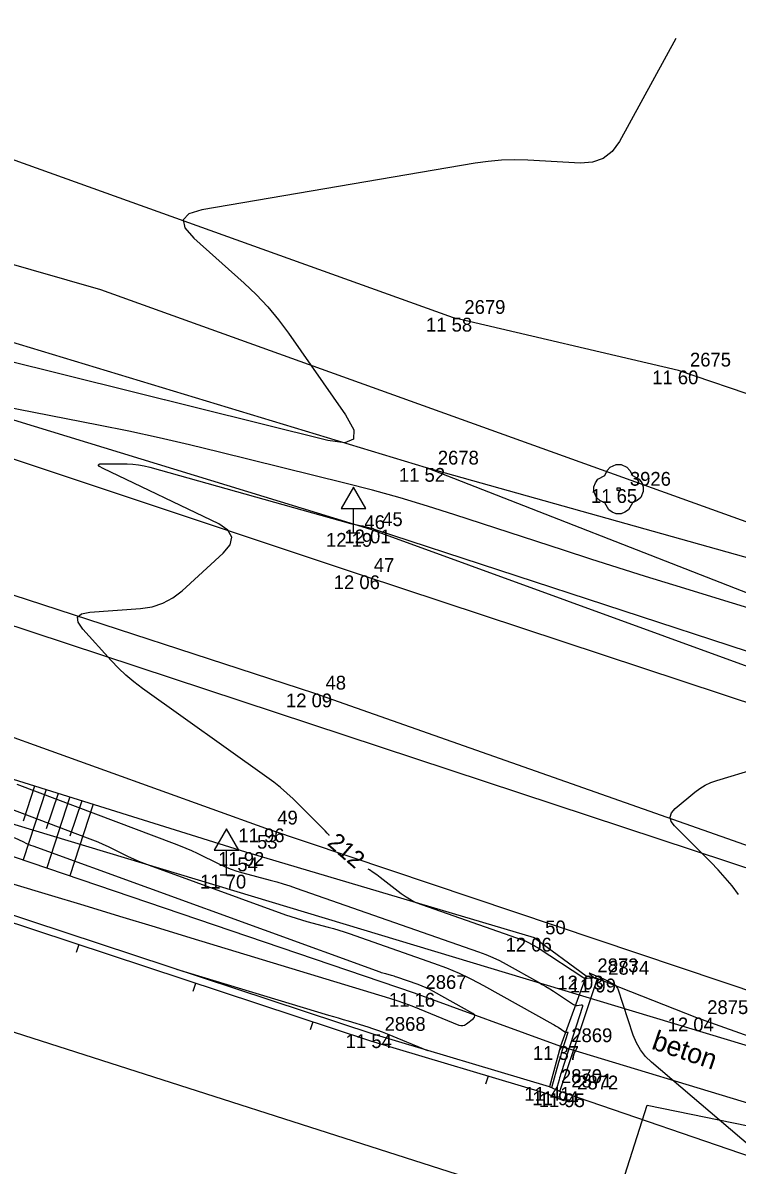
# Model space of a CAD drawing. Extents: x -703403 to -701924, y -1022520 to -1021856.
# Drawn here: x -702048.06 to -702033.55, y -1022309.37 to -1022286.17 of the extents above; entities that cross this region are included whole.
import ezdxf

# ---------------------------------------------------------------- set-up
doc = ezdxf.new("R2010")
doc.units = 0
for name, color, linetype in [('Ex_Contour Labels', 7, 'Continuous'), ('Ex_Major Contours', 7, 'Continuous'), ('Ex_Minor Contours', 7, 'Continuous'), ('Z_betonova_konstrukce', 7, 'Continuous'), ('Z_body', 7, 'Continuous'), ('Z_body_cisla', 7, 'Continuous'), ('Z_body_vysky_redukovane', 7, 'Continuous'), ('Z_dopravni_znacky', 7, 'Continuous'), ('Z_hrany_paty', 7, 'Continuous'), ('Z_katastr_hranice', 7, 'Continuous'), ('Z_katastr_vnitrni_kresba', 7, 'Continuous'), ('Z_komunikace', 7, 'Continuous'), ('Z_komunikace_osa', 7, 'Continuous'), ('Z_ploty', 7, 'Continuous'), ('Z_ploty_znacky', 7, 'Continuous'), ('Z_pole_rozhranni', 7, 'Continuous'), ('Z_popisy', 7, 'Continuous'), ('Z_propustek', 7, 'Continuous'), ('Z_rozhranni', 7, 'Continuous'), ('Z_technicke_srafy', 7, 'Continuous'), ('Z_vstupy', 7, 'Continuous'), ('Z_zelen_jednotliva', 7, 'Continuous')]:
    doc.layers.add(name, color=color, linetype=linetype)

# ---------------------------------------------------------------- blocks, each defined once
blk = doc.blocks.new('POINT_DISPLAY')
blk.add_line((0, 0), (0, 0))
blk = doc.blocks.new('Z24')
for p, q in [((-0.17, 0.45), (-0.05, 0.5)), ((-0.05, 0.5), (0.05, 0.5)), ((0.05, 0.5), (0.17, 0.45)), ((-0.42, 0.2), (-0.28, 0.28)), ((-0.28, 0.28), (-0.23, 0.38)), ((-0.23, 0.38), (-0.17, 0.45)), ((0.17, 0.45), (0.23, 0.38)), ((0.23, 0.38), (0.28, 0.28)), ((0.28, 0.28), (0.42, 0.2)), ((-0.5, 0.05), (-0.47, 0.13)), ((-0.5, -0.05), (-0.5, 0.05)), ((-0.47, 0.13), (-0.42, 0.2)), ((-0.03, -0.03), (-0.03, 0.03)), ((-0.03, 0.03), (0.03, 0.03)), ((0.03, 0.03), (0.03, -0.03)), ((0.42, 0.2), (0.47, 0.13)), ((0.47, 0.13), (0.5, 0.05)), ((0.5, 0.05), (0.5, -0.05)), ((-0.45, -0.17), (-0.5, -0.05)), ((-0.38, -0.23), (-0.45, -0.17)), ((-0.28, -0.28), (-0.38, -0.23)), ((0.03, -0.03), (-0.03, -0.03)), ((0.38, -0.23), (0.28, -0.28)), ((0.45, -0.17), (0.38, -0.23)), ((0.5, -0.05), (0.45, -0.17)), ((-0.2, -0.42), (-0.28, -0.28)), ((-0.13, -0.47), (-0.2, -0.42)), ((0.2, -0.42), (0.13, -0.47)), ((0.28, -0.28), (0.2, -0.42)), ((-0.05, -0.5), (-0.13, -0.47)), ((0.05, -0.5), (-0.05, -0.5)), ((0.13, -0.47), (0.05, -0.5))]:
    blk.add_line(p, q)
blk = doc.blocks.new('Z527')
for p, q in [((0, 0.93), (-0.25, 0.5)), ((0.25, 0.5), (0, 0.93)), ((-0.25, 0.5), (0.25, 0.5)), ((0, 0), (0, 0.5)), ((-0.13, 0), (0.13, 0))]:
    blk.add_line(p, q)
blk = doc.blocks.new('Z210')
blk.add_line((0, 0), (0, 0.17))

msp = doc.modelspace()

# ---------------------------------------------------------------- linework, layer by layer
at = {"layer": 'Ex_Major Contours'}
for points in [[(-702041.834, -1022302.671), (-702041.835, -1022302.67), (-702041.876, -1022302.624), (-702041.918, -1022302.581), (-702042.569, -1022301.932), (-702042.695, -1022301.812), (-702042.825, -1022301.698), (-702042.959, -1022301.589), (-702043.098, -1022301.486), (-702045.628, -1022299.685), (-702045.799, -1022299.556), (-702045.961, -1022299.419), (-702046.116, -1022299.273), (-702046.263, -1022299.119), (-702046.835, -1022298.484), (-702046.933, -1022298.343), (-702046.943, -1022298.238), (-702046.863, -1022298.169), (-702046.694, -1022298.136), (-702045.667, -1022298.065), (-702045.432, -1022298.029), (-702045.213, -1022297.957), (-702045.01, -1022297.849), (-702044.823, -1022297.703), (-702043.989, -1022296.943), (-702043.846, -1022296.769), (-702043.813, -1022296.612), (-702043.89, -1022296.472), (-702044.077, -1022296.347), (-702046.424, -1022295.221), (-702046.501, -1022295.177), (-702046.523, -1022295.146), (-702046.489, -1022295.128), (-702046.401, -1022295.123), (-702045.935, -1022295.128), (-702045.82, -1022295.133), (-702045.705, -1022295.146), (-702045.591, -1022295.166), (-702045.479, -1022295.193), (-702041.4, -1022296.336), (-702041.375, -1022296.342), (-702041.351, -1022296.348), (-702041.327, -1022296.354), (-702041.302, -1022296.359), (-702041.203, -1022296.378), (-702041.179, -1022296.383), (-702041.155, -1022296.388), (-702041.132, -1022296.394), (-702041.108, -1022296.399), (-702041.014, -1022296.423), (-702040.991, -1022296.429), (-702040.967, -1022296.435), (-702040.944, -1022296.442), (-702040.921, -1022296.45), (-702033.347, -1022298.929)], [(-702033.274, -1022308.995), (-702035.289, -1022307.279), (-702035.412, -1022307.16), (-702035.515, -1022307.028), (-702035.598, -1022306.883), (-702035.662, -1022306.725), (-702035.969, -1022305.797), (-702035.98, -1022305.769), (-702035.997, -1022305.745), (-702036.017, -1022305.724), (-702036.041, -1022305.707), (-702036.148, -1022305.645), (-702036.175, -1022305.63), (-702036.203, -1022305.616), (-702036.231, -1022305.603), (-702036.259, -1022305.591), (-702036.535, -1022305.477), (-702036.55, -1022305.472), (-702036.556, -1022305.472), (-702036.553, -1022305.477), (-702036.542, -1022305.487), (-702036.479, -1022305.539), (-702036.468, -1022305.551), (-702036.465, -1022305.56), (-702036.472, -1022305.566), (-702036.488, -1022305.569), (-702036.595, -1022305.58), (-702036.619, -1022305.58), (-702036.642, -1022305.577), (-702036.664, -1022305.569), (-702036.685, -1022305.558), (-702037.574, -1022304.974), (-702037.599, -1022304.958), (-702037.624, -1022304.942), (-702037.65, -1022304.927), (-702037.676, -1022304.912), (-702037.78, -1022304.854), (-702037.807, -1022304.84), (-702037.834, -1022304.827), (-702037.861, -1022304.815), (-702037.889, -1022304.805), (-702039.955, -1022304.083), (-702040.066, -1022304.04), (-702040.172, -1022303.987), (-702040.274, -1022303.927), (-702040.371, -1022303.858), (-702040.801, -1022303.526), (-702040.871, -1022303.473), (-702040.943, -1022303.422), (-702041.016, -1022303.374), (-702041.041, -1022303.359)]]:
    msp.add_lwpolyline(points, dxfattribs=at)
at = {"layer": 'Ex_Minor Contours'}
for points in [[(-702034.795, -1022286.488), (-702035.943, -1022288.577), (-702036.089, -1022288.781), (-702036.27, -1022288.922), (-702036.486, -1022289.001), (-702036.736, -1022289.018), (-702037.805, -1022288.959), (-702038.072, -1022288.952), (-702038.338, -1022288.96), (-702038.604, -1022288.983), (-702038.868, -1022289.02), (-702044.42, -1022289.969), (-702044.684, -1022290.048), (-702044.799, -1022290.17), (-702044.766, -1022290.334), (-702044.585, -1022290.541), (-702043.564, -1022291.455), (-702043.316, -1022291.69), (-702043.083, -1022291.938), (-702042.865, -1022292.199), (-702042.661, -1022292.474), (-702041.507, -1022294.128), (-702041.337, -1022294.437), (-702041.34, -1022294.628), (-702041.516, -1022294.698), (-702041.866, -1022294.65), (-702048.5, -1022293.003)], [(-702030.013, -1022299.075), (-702034.861, -1022297.585), (-702035.416, -1022297.412), (-702035.971, -1022297.238), (-702036.524, -1022297.061), (-702037.077, -1022296.881), (-702039.286, -1022296.158), (-702039.84, -1022295.983), (-702040.396, -1022295.817), (-702040.956, -1022295.662), (-702041.518, -1022295.517), (-702044.06, -1022294.886), (-702044.673, -1022294.738), (-702045.287, -1022294.598), (-702045.903, -1022294.465), (-702046.521, -1022294.34), (-702050.119, -1022293.637)], [(-702052.253, -1022300.639), (-702046.746, -1022302.719), (-702046.64, -1022302.761), (-702046.534, -1022302.805), (-702046.43, -1022302.851), (-702046.326, -1022302.899), (-702045.914, -1022303.098), (-702045.81, -1022303.146), (-702045.706, -1022303.192), (-702045.6, -1022303.235), (-702045.493, -1022303.275), (-702042.72, -1022304.282), (-702042.614, -1022304.319), (-702042.507, -1022304.354), (-702042.4, -1022304.387), (-702042.292, -1022304.417), (-702041.857, -1022304.533), (-702041.749, -1022304.563), (-702041.641, -1022304.595), (-702041.534, -1022304.629), (-702041.428, -1022304.665), (-702039.715, -1022305.263), (-702039.454, -1022305.36), (-702039.198, -1022305.469), (-702038.947, -1022305.588), (-702038.701, -1022305.719), (-702037.293, -1022306.506), (-702037.266, -1022306.521), (-702037.24, -1022306.536), (-702037.215, -1022306.552), (-702037.189, -1022306.569), (-702037.049, -1022306.661), (-702037.043, -1022306.664), (-702037.037, -1022306.666), (-702037.031, -1022306.667), (-702037.024, -1022306.667), (-702036.996, -1022306.664), (-702036.991, -1022306.664), (-702036.987, -1022306.666), (-702036.986, -1022306.67), (-702036.987, -1022306.676), (-702037.102, -1022307.036), (-702037.122, -1022307.098), (-702037.141, -1022307.16), (-702037.16, -1022307.223), (-702037.178, -1022307.285), (-702037.324, -1022307.795)], [(-702033.525, -1022303.869), (-702033.656, -1022303.697), (-702033.793, -1022303.53), (-702033.937, -1022303.369), (-702034.088, -1022303.213), (-702034.826, -1022302.478), (-702034.894, -1022302.387), (-702034.914, -1022302.299), (-702034.887, -1022302.212), (-702034.811, -1022302.128), (-702034.414, -1022301.795), (-702034.311, -1022301.718), (-702034.203, -1022301.652), (-702034.088, -1022301.597), (-702033.967, -1022301.554), (-702031.551, -1022300.827)], [(-702048.177, -1022301.629), (-702044.982, -1022302.835), (-702044.864, -1022302.881), (-702044.747, -1022302.93), (-702044.631, -1022302.981), (-702044.517, -1022303.035), (-702044.06, -1022303.255), (-702043.945, -1022303.308), (-702043.827, -1022303.354), (-702043.708, -1022303.395), (-702043.586, -1022303.431), (-702043.032, -1022303.579), (-702042.899, -1022303.615), (-702042.767, -1022303.655), (-702042.635, -1022303.696), (-702042.505, -1022303.741), (-702038.802, -1022305.034), (-702038.658, -1022305.088), (-702038.516, -1022305.148), (-702038.377, -1022305.214), (-702038.241, -1022305.286), (-702037.586, -1022305.652), (-702037.509, -1022305.696), (-702037.434, -1022305.741), (-702037.358, -1022305.788), (-702037.284, -1022305.835), (-702036.874, -1022306.105), (-702036.857, -1022306.114), (-702036.839, -1022306.12), (-702036.82, -1022306.123), (-702036.801, -1022306.123), (-702036.72, -1022306.114), (-702036.704, -1022306.115), (-702036.693, -1022306.121), (-702036.69, -1022306.132), (-702036.693, -1022306.149), (-702037.125, -1022307.495), (-702037.136, -1022307.529), (-702037.146, -1022307.563), (-702037.156, -1022307.598), (-702037.166, -1022307.632), (-702037.225, -1022307.838)], [(-702053.415, -1022302.106), (-702047.538, -1022303.873), (-702046.814, -1022304.091), (-702046.091, -1022304.31), (-702045.368, -1022304.529), (-702044.644, -1022304.749), (-702040.613, -1022305.976), (-702040.461, -1022306.024), (-702040.309, -1022306.076), (-702040.159, -1022306.132), (-702040.01, -1022306.191), (-702039.204, -1022306.523), (-702039.163, -1022306.535), (-702039.123, -1022306.535), (-702039.085, -1022306.524), (-702039.049, -1022306.501), (-702038.908, -1022306.389), (-702038.882, -1022306.362), (-702038.875, -1022306.336), (-702038.886, -1022306.312), (-702038.916, -1022306.289), (-702039.716, -1022305.842), (-702039.792, -1022305.802), (-702039.869, -1022305.765), (-702039.948, -1022305.731), (-702040.028, -1022305.701), (-702040.459, -1022305.551), (-702040.487, -1022305.541), (-702040.515, -1022305.532), (-702040.544, -1022305.524), (-702040.573, -1022305.516), (-702040.688, -1022305.485), (-702040.716, -1022305.477), (-702040.745, -1022305.469), (-702040.773, -1022305.46), (-702040.801, -1022305.45), (-702047.845, -1022302.892), (-702047.893, -1022302.874), (-702047.942, -1022302.854), (-702047.99, -1022302.833), (-702048.037, -1022302.811), (-702048.225, -1022302.72)], [(-702044.937, -1022305.39), (-702041.85, -1022306.319), (-702041.75, -1022306.349), (-702041.65, -1022306.379), (-702041.551, -1022306.409), (-702041.451, -1022306.439), (-702041.052, -1022306.561), (-702040.953, -1022306.592), (-702040.854, -1022306.626), (-702040.757, -1022306.662), (-702040.66, -1022306.701), (-702039.838, -1022307.039)]]:
    msp.add_lwpolyline(points, dxfattribs=at)
at = {"layer": 'Z_betonova_konstrukce'}
for p, q in [((-702037.15, -1022307.87), (-702036.39, -1022305.58)), ((-702036.62, -1022305.52), (-702037.14, -1022306.95)), ((-702036.62, -1022305.52), (-702036.39, -1022305.58)), ((-702037.14, -1022306.95), (-702037.36, -1022307.78))]:
    msp.add_line(p, q, dxfattribs=at)
at = {"layer": 'Z_hrany_paty'}
for p, q in [((-702039.86, -1022295.21), (-702052.88, -1022291.26)), ((-702040.99, -1022296.46), (-702053.28, -1022292.7)), ((-702022.69, -1022301.91), (-702039.86, -1022295.21)), ((-702031.79, -1022297.47), (-702039.86, -1022295.21)), ((-702029.38, -1022300.69), (-702040.99, -1022296.46)), ((-702043.53, -1022303.01), (-702054.01, -1022299.73)), ((-702049.82, -1022302.57), (-702040.11, -1022305.87)), ((-702037.67, -1022304.75), (-702043.53, -1022303.01)), ((-702037.67, -1022304.75), (-702036.62, -1022305.52)), ((-702040.11, -1022305.87), (-702037.14, -1022306.95))]:
    msp.add_line(p, q, dxfattribs=at)
at = {"layer": 'Z_katastr_hranice'}
for p, q in [((-702046.47, -1022291.59), (-702114.48, -1022272.11)), ((-702081.55, -1022287.42), (-702015.88, -1022309.1)), ((-701974.6, -1022317.46), (-702046.47, -1022291.59)), ((-702016.82, -1022311.93), (-702057.09, -1022299.78)), ((-702036.14, -1022310.54), (-702035.38, -1022308.15)), ((-702035.38, -1022308.15), (-702016.82, -1022311.93))]:
    msp.add_line(p, q, dxfattribs=at)
at = {"layer": 'Z_katastr_vnitrni_kresba'}
msp.add_line((-702055.91, -1022304.21), (-702036.14, -1022310.54), dxfattribs=at)
at = {"layer": 'Z_komunikace'}
for p, q in [((-702041.16, -1022297.39), (-702053.32, -1022293.34)), ((-702029.57, -1022301.23), (-702041.16, -1022297.39)), ((-702043.12, -1022302.53), (-702053.67, -1022298.73)), ((-702031.31, -1022306.5), (-702043.12, -1022302.53))]:
    msp.add_line(p, q, dxfattribs=at)
at = {"layer": 'Z_komunikace_osa'}
for p, q in [((-702042.13, -1022299.79), (-702054.33, -1022295.82)), ((-702030.56, -1022303.86), (-702042.13, -1022299.79))]:
    msp.add_line(p, q, dxfattribs=at)
at = {"layer": 'Z_ploty'}
for p, q in [((-702040.99, -1022306.85), (-702055.98, -1022301.9)), ((-702040.94, -1022306.71), (-702055.93, -1022301.76)), ((-702037.36, -1022307.78), (-702040.94, -1022306.71)), ((-702037.41, -1022307.92), (-702040.99, -1022306.85)), ((-702037.21, -1022308.01), (-702037.41, -1022307.92)), ((-702037.15, -1022307.87), (-702037.36, -1022307.78)), ((-702037.02, -1022307.91), (-702037.15, -1022307.87)), ((-702037.07, -1022308.06), (-702037.02, -1022307.91)), ((-702037.07, -1022308.06), (-702037.21, -1022308.01))]:
    msp.add_line(p, q, dxfattribs=at)
at = {"layer": 'Z_pole_rozhranni'}
for p, q in [((-702039.31, -1022292.16), (-702053.05, -1022287.23)), ((-702034.74, -1022293.23), (-702039.31, -1022292.16)), ((-702021.67, -1022297.67), (-702034.74, -1022293.23))]:
    msp.add_line(p, q, dxfattribs=at)
at = {"layer": 'Z_propustek'}
msp.add_line((-702037.14, -1022306.95), (-702032.28, -1022308.43), dxfattribs=at)
at = {"layer": 'Z_rozhranni'}
for p, q in [((-702036.39, -1022305.58), (-702034.38, -1022306.37)), ((-702034.38, -1022306.37), (-702032.17, -1022307.16))]:
    msp.add_line(p, q, dxfattribs=at)
at = {"layer": 'Z_technicke_srafy'}
for p, q in [((-702047.82, -1022301.67), (-702048.05, -1022302.38)), ((-702047.58, -1022301.74), (-702048.05, -1022303.17)), ((-702047.34, -1022301.82), (-702047.58, -1022302.54)), ((-702047.1, -1022301.89), (-702047.57, -1022303.33)), ((-702046.86, -1022301.97), (-702047.1, -1022302.69)), ((-702046.63, -1022302.04), (-702047.1, -1022303.49))]:
    msp.add_line(p, q, dxfattribs=at)
at = {"layer": 'Z_vstupy'}
msp.add_line((-702037.02, -1022307.91), (-702032.88, -1022309.33), dxfattribs=at)

# ---------------------------------------------------------------- block references
at = {"layer": 'Z_body'}
for p in [(-702039.31, -1022292.16), (-702034.74, -1022293.23), (-702039.86, -1022295.21), (-702035.96, -1022295.64), (-702041.34, -1022296.53), (-702040.99, -1022296.46), (-702041.16, -1022297.39), (-702042.13, -1022299.79), (-702043.12, -1022302.53), (-702043.53, -1022303.01), (-702043.92, -1022303.47), (-702037.67, -1022304.75), (-702036.62, -1022305.52), (-702036.39, -1022305.58), (-702040.11, -1022305.87), (-702034.38, -1022306.37), (-702040.94, -1022306.71), (-702037.14, -1022306.95), (-702037.36, -1022307.78), (-702037.15, -1022307.87), (-702037.02, -1022307.91)]:
    msp.add_blockref('POINT_DISPLAY', p, dxfattribs=at)
at = {"layer": 'Z_dopravni_znacky'}
for p in [(-702041.34, -1022296.53), (-702043.92, -1022303.47)]:
    msp.add_blockref('Z527', p, dxfattribs=at)
at = {"layer": 'Z_ploty_znacky'}
for p, rotation in [((-702046.92, -1022304.89), 161.7), ((-702044.55, -1022305.68), 161.7), ((-702042.17, -1022306.46), 161.7), ((-702038.61, -1022307.56), 163.3)]:
    msp.add_blockref('Z210', p, dxfattribs=dict(at, rotation=rotation))
at = {"layer": 'Z_zelen_jednotliva'}
msp.add_blockref('Z24', (-702035.96, -1022295.64), dxfattribs=at)

# ---------------------------------------------------------------- texts
at = {"layer": 'Ex_Contour Labels'}
msp.add_text('212', height=0.35, rotation=319.0617, dxfattribs=at).set_placement((-702041.894, -1022302.852))
at = {"layer": 'Z_body_cisla'}
for s, p in [('2679', (-702039.09, -1022292.08)), ('2675', (-702034.51, -1022293.15)), ('2678', (-702039.63, -1022295.14)), ('3926', (-702035.73, -1022295.57)), ('45', (-702040.76, -1022296.39)), ('46', (-702041.12, -1022296.45)), ('47', (-702040.93, -1022297.32)), ('48', (-702041.91, -1022299.71)), ('49', (-702042.89, -1022302.45)), ('53', (-702043.3, -1022302.94)), ('54', (-702043.7, -1022303.4)), ('50', (-702037.45, -1022304.68)), ('2873', (-702036.39, -1022305.45)), ('2874', (-702036.17, -1022305.5)), ('2867', (-702039.88, -1022305.79)), ('2875', (-702034.16, -1022306.3)), ('2868', (-702040.71, -1022306.64)), ('2869', (-702036.92, -1022306.87)), ('2870', (-702037.13, -1022307.7)), ('2871', (-702036.92, -1022307.79)), ('2872', (-702036.8, -1022307.83))]:
    msp.add_text(s, height=0.28, dxfattribs=at).set_placement(p)
at = {"layer": 'Z_body_vysky_redukovane'}
for s, p in [('11 58', (-702039.87, -1022292.44)), ('11 60', (-702035.277, -1022293.51)), ('11 52', (-702040.42, -1022295.49)), ('11 65', (-702036.52, -1022295.92)), ('12 19', (-702041.9, -1022296.81)), ('12 01', (-702041.527, -1022296.74)), ('12 06', (-702041.743, -1022297.67)), ('12 09', (-702042.713, -1022300.07)), ('11 96', (-702043.68, -1022302.81)), ('11 92', (-702044.09, -1022303.29)), ('11 70', (-702044.457, -1022303.75)), ('12 06', (-702038.253, -1022305.03)), ('12 03', (-702037.203, -1022305.8)), ('11 99', (-702036.95, -1022305.86)), ('11 16', (-702040.623, -1022306.15)), ('12 04', (-702034.963, -1022306.65)), ('11 54', (-702041.5, -1022306.99)), ('11 37', (-702037.7, -1022307.23)), ('11 41', (-702037.873, -1022308.06)), ('11 94', (-702037.71, -1022308.15)), ('11 95', (-702037.58, -1022308.19))]:
    msp.add_text(s, height=0.28, dxfattribs=at).set_placement(p)
at = {"layer": 'Z_popisy'}
msp.add_text('beton', height=0.4, rotation=341.1, dxfattribs=at).set_placement((-702035.31, -1022307))

doc.saveas('drawing.dxf')
